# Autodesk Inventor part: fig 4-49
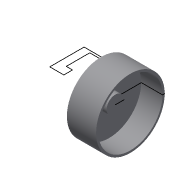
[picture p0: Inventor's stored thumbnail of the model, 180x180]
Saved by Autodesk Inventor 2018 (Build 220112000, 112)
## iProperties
Created: 2004-05
Part Number: fig 4-49
Document SubType Name: Modeling
Designer: CADCIM Technologies
Manufacturer: Standard
Standards Organization: Custom
Density: 1 g/cm^3
Material: Generic
Appearance: Default
Author: CADCIM Technologies
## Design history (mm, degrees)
sketch "Sketch1"
  geometry: L1 (37.08, 12.209)-(23.643, 12.209); L2 (23.643, 12.209)-(23.643, 45.026); L3 (23.643, 45.026)-(51.55, 45.026); L4 (51.55, 45.026)-(51.55, 42.959); L5 (51.55, 42.959)-(31.137, 42.959); L6 (31.137, 42.959)-(31.137, 20.478); L7 (31.137, 20.478)-(37.08, 20.478); L8 (37.08, 20.478)-(37.08, 12.209); L9 (86.437, 12.209)-(73, 12.209); L10 (73, 12.209)-(73, 45.026); L11 (73, 45.026)-(100.907, 45.026); L12 (100.907, 45.026)-(100.907, 42.959); L13 (100.907, 42.959)-(80.494, 42.959); L14 (80.494, 42.959)-(80.494, 20.478); L15 (80.494, 20.478)-(86.437, 20.478); L16 (86.437, 20.478)-(86.437, 12.209)
  constraints: 32 end point, 12 parallel, 2 horizontal, 2 perpendicular
revolve "Revolution1" sketch "Sketch1" stored, may be unused: angle "d0" = 90 deg
body "Solid1"
